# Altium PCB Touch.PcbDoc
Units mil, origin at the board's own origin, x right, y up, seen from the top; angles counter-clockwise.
Board outline 18895 x 844.38 mil, 2 copper layers (Top Layer, Bottom Layer); 105 components, 62 nets, 324 pads, 237 vias.
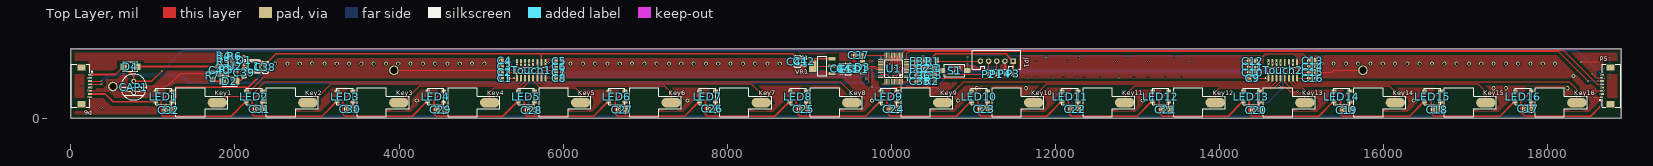
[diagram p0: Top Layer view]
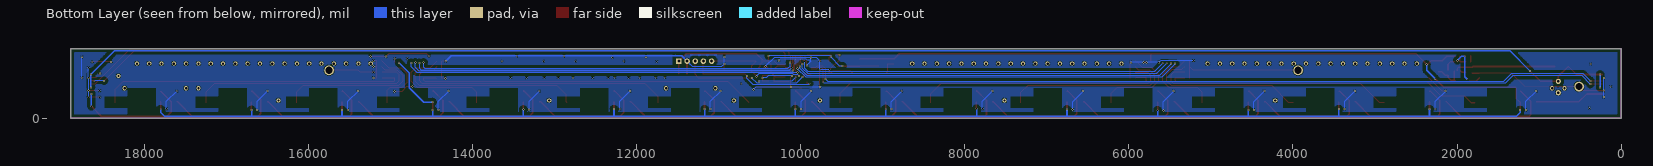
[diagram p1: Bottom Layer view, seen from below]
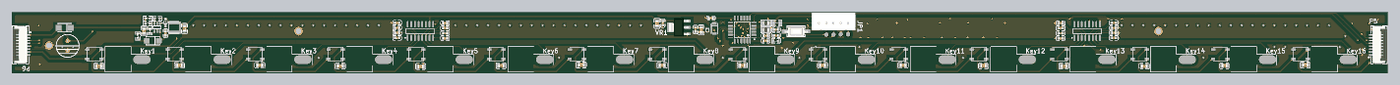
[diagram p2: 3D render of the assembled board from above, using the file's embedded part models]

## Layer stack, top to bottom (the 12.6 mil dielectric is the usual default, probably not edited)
Top Solder: solder mask 0.4, Solder Resist, Dk 3.5
Top Layer: signal copper 1.4
Dielectric 1: dielectric 12.6, FR-4, Dk 4.8
Bottom Layer: signal copper 1.4
Bottom Solder: solder mask 0.4, Solder Resist, Dk 3.5

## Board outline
0,0 18895,0 18895,844.38 0,844.38

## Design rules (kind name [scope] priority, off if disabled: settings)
Clearance CU [InNamedPolygon('POWER_GND_L02_P000')] p1: gap=39.37
Clearance CU2 [InNamedPolygon('POWER_GND_L01_P002')] p2: gap=39.37
Clearance [All] p3: gap=6
PolygonConnect [All] p1: connectstyle=Relief reliefconductorwidth=10 reliefentries=4 polygonreliefangle="90 Angle" airgapwidth=10
RoutingVias [All] p1: holewidth=11.81 width=23.62 viastyle="Through Hole" minholewidth=11.81 minwidth=23.62 maxholewidth=19.68 maxwidth=50
SolderMaskExpansion [All] p1: expansion=4
Width [All] p1: maxlimit=20 minlimit=6 preferedwidth=10
30 further rules are at their usual default settings.

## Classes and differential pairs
component class MCU: C33 C34 C35 C36 C37 FB1 FB2 JP1 P1 P2 P3 P4 R1 R2 S1 U1
component class POWER: C38 C39 C40 C41 C42 C43 C44 CAP1 D1 D2 D3 D4 ESD1 L1 P5 P6 R3 R4 R5 R6 R7 U2 VR1
component class WS2812: C1 C2 C3 C4 C5 C6 C7 C8 C9 C10 C11 C12 C13 C14 C15 C16 C17 C18 C19 C20 C21 C22 C23 C24 C25 C26 C27 C28 C29 C30 C31 C32 Key1 Key2 Key3 Key4 Key5 Key6 Key7 Key8 Key9 Key10 Key11 Key12 Key13 Key14 Key15 Key16 LED1 LED2 LED3 LED4 LED5 LED6 LED7 LED8 LED9 LED10 LED11 LED12 LED13 LED14 LED15 LED16 Touch1 Touch2

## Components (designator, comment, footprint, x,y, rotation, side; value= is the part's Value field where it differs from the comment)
C1 "10pF (100) 5% 50V" 0603_C 5290,489.38 r180 top
C2 "10pF (100) 5% 50V" 0603_C 5290,559.38 r180 top
C3 "10pF (100) 5% 50V" 0603_C 5290,629.38 r180 top
C4 "10pF (100) 5% 50V" 0603_C 5290,699.38 r180 top
C5 "10pF (100) 5% 50V" 0603_C 5950,694.38 r0 top
C6 "10pF (100) 5% 50V" 0603_C 5950,624.38 r0 top
C7 "10pF (100) 5% 50V" 0603_C 5950,554.38 r0 top
C8 "10pF (100) 5% 50V" 0603_C 5950,484.38 r0 top
C9 "10pF (100) 5% 50V" 0603_C 14405,484.38 r180 top
C10 "10pF (100) 5% 50V" 0603_C 14405,554.38 r180 top
C11 "10pF (100) 5% 50V" 0603_C 14405,624.38 r180 top
C12 "10pF (100) 5% 50V" 0603_C 14405,694.38 r180 top
C13 "10pF (100) 5% 50V" 0603_C 15135,699.38 r0 top
C14 "10pF (100) 5% 50V" 0603_C 15135,629.38 r0 top
C15 "10pF (100) 5% 50V" 0603_C 15135,559.38 r0 top
C16 "10pF (100) 5% 50V" 0603_C 15135,489.38 r0 top
C17 "10uF (106) 10% 25V" 0805_C 17765,114.38 r0 top
C18 "10uF (106) 10% 25V" 0805_C 16656.67,104.38 r0 top
C19 "10uF (106) 10% 25V" 0805_C 15553.33,99.38 r0 top
C20 "10uF (106) 10% 25V" 0805_C 14450,99.38 r0 top
C21 "10uF (106) 10% 25V" 0805_C 13345,105 r0 top
C22 "10uF (106) 10% 25V" 0805_C 12240,110 r0 top
C23 "10uF (106) 10% 25V" 0805_C 11135,110 r0 top
C24 "10uF (106) 10% 25V" 0805_C 10030,110 r0 top
C25 "10uF (106) 10% 25V" 0805_C 8930,110 r0 top
C26 "10uF (106) 10% 25V" 0805_C 7820,115 r0 top
C27 "10uF (106) 10% 25V" 0805_C 6720,105 r0 top
C28 "10uF (106) 10% 25V" 0805_C 5615,95 r0 top
C29 "10uF (106) 10% 25V" 0805_C 4510,100 r0 top
C30 "10uF (106) 10% 25V" 0805_C 3405,110 r0 top
C31 "10uF (106) 10% 25V" 0805_C 2300,110 r0 top
C32 "10uF (106) 10% 25V" 0805_C 1195,99.38 r0 top
C33 "100nF (104) 10% 50V" 0603_C 10495,524.38 r0 top
C34 "100nF (104) 10% 50V" 0603_C 10495,604.38 r180 top
C35 "100nF (104) 10% 50V" 0603_C 10355,449.38 r0 top
C36 "100nF (104) 10% 50V" 0603_C 10355,519.38 r0 top
C37 "100nF (104) 10% 50V" 0603_C 9600,764.38 r180 top
C38 "22uF (226) 20% 25V" 0805_C 2370,619.38 r270 top
C39 "22nF (223) 10% 50V" 0603_C 2110,554.38 r270 top
C40 "10uF (106) 10% 25V" 0805_C 1815,584.38 r90 top
C41 "10uF (106) 10% 25V" 0805_C 8860,689.38 r90 top
C42 "100nF (104) 10% 50V" 0603_C 8940,694.38 r90 top
C43 "10uF (106) 10% 25V" 0805_C 9470,599.38 r90 top
C44 "100nF (104) 10% 50V" 0603_C 9390,604.38 r90 top
CAP1 "CAP" 8X12_CAP 765,379.38 r270 top
D1 "1N4148WS T4" SOD-323 2110,704.38 r90 top
D2 "SS210" SMA(DO-214AC)_S1 1935,449.38 r180 top
D3 "ZMM3V3" LL-34 9650,619.38 r270 top
D4 "M7" SMA(DO-214AC)_S1 725,629.38 r180 top
ESD1 "ESD5Z12T" SOD-523 9550,569.38 r90 top
FB1 "100Ω ±25% 100MHz" 0805_L 10355,694.38 r180 top
FB2 "100Ω ±25% 100MHz" 0805_L 10355,599.38 r180 top
JP1 "HDR-1X5" XH2.54-LI-5P 11285,694.38 r180 top
Key1 "TP" SPRING_TOUCH 1785,189.38 r90 top
Key2 "TP" SPRING_TOUCH 2888.33,189.38 r90 top
Key3 "TP" SPRING_TOUCH 3996.67,189.38 r90 top
Key4 "TP" SPRING_TOUCH 5105,189.38 r90 top
Key5 "TP" SPRING_TOUCH 6213.33,189.38 r90 top
Key6 "TP" SPRING_TOUCH 7316.67,189.38 r90 top
Key7 "TP" SPRING_TOUCH 8415,189.38 r90 top
Key8 "TP" SPRING_TOUCH 9518.33,189.38 r90 top
Key9 "TP" SPRING_TOUCH 10626.67,189.38 r90 top
Key10 "TP" SPRING_TOUCH 11735,189.38 r90 top
Key11 "TP" SPRING_TOUCH 12843.33,189.38 r90 top
Key12 "TP" SPRING_TOUCH 13946.67,189.38 r90 top
Key13 "TP" SPRING_TOUCH 15040,189.38 r90 top
Key14 "TP" SPRING_TOUCH 16143.33,189.38 r90 top
Key15 "TP" SPRING_TOUCH 17246.67,189.38 r90 top
Key16 "TP" SPRING_TOUCH 18355,189.38 r90 top
L1 "4.7uH ±10%" L_4030 2308.74,553.71 r90 top
LED1 "WS2812B" WS2812 1230.32,362.41 r180 top
LED2 "WS2812B" WS2812 2334.94,362.41 r180 top
LED3 "WS2812B" WS2812 3439.57,362.41 r180 top
LED4 "WS2812B" WS2812 4544.2,362.41 r180 top
LED5 "WS2812B" WS2812 5648.82,362.41 r180 top
LED6 "WS2812B" WS2812 6753.45,362.41 r180 top
LED7 "WS2812B" WS2812 7858.08,362.41 r180 top
LED8 "WS2812B" WS2812 8962.71,362.41 r180 top
LED9 "WS2812B" WS2812 10067.33,362.41 r180 top
LED10 "WS2812B" WS2812 11171.96,362.41 r180 top
LED11 "WS2812B" WS2812 12276.59,362.41 r180 top
LED12 "WS2812B" WS2812 13381.21,362.41 r180 top
LED13 "WS2812B" WS2812 14485.84,362.41 r180 top
LED14 "WS2812B" WS2812 15590.47,362.41 r180 top
LED15 "WS2812B" WS2812 16695.1,362.41 r180 top
LED16 "WS2812B" WS2812 17799.72,362.41 r180 top
P1 "TP" TP 11285,534.38 r180 top
P2 "TP" TP 11185,534.38 r180 top
P3 "TP" TP 11485,539.38 r180 top
P4 "TP" TP 11385,539.38 r180 top
P5 "Header 8" FPC1.0-2H-WS-8P 18765,393.7 r90 top
P6 "Header 8" FPC1.0-2H-WS-8P 130,393.7 r270 top
R1 "10KΩ (1002) ±1%" 0805_R 10505,694.38 r180 top
R2 "10KΩ (1002) ±1%" 0603_R 10495,449.38 r180 top
R3 "100KΩ (1003) ±1%" 0603_R 1895,589.38 r90 top
R4 "2KΩ (2001) ±1%" 0603_R 1865,759.38 r0 top
R5 "7.5KΩ (7501) ±1%" 0603_R 1865,689.38 r180 top
R6 "49.9KΩ (4992) ±1%" 0603_R 1995,754.38 r0 top
R7 "0Ω (0R0) ±1%" 0603_R 1730,519.38 r270 top
S1 "SW-SPST" "TSW SMD-3*6*2.5" 10772.31,580.16 r0 top
Touch1 "BS818A-2" SO-16_N 5610,584.38 r90 top
Touch2 "BS818A-2" SO-16_N 14770,584.38 r90 top
U1 "STM32F030C8T6" LQFP-48_7x7x05P 10030,604.38 r90 top
U2 "MP2359DJ-LF-Z" SOT-23-6 1995,634.38 r90 top
VR1 "AMS1117-3.3" SOT-223 9160,634.38 r0 top

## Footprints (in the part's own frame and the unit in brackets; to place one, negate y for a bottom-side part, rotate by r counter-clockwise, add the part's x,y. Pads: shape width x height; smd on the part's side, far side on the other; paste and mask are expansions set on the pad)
8X12_CAP [mm]
  round 1.6 hole 0.75: 1(-1.75,0) 2(1.75,0)
  silkscreen extent -4,-4 4,4
0603_C [mm]
  rect 0.93x0.98 smd: 1(-0.77,0) 2(0.77,0)
  silkscreen extent -1.53,-0.79 1.54,0.79, body extent -0.8,-0.4 0.8,0.4, height 0.3
0603_R [mm]
  rect 0.93x0.98 smd: 1(-0.77,0) 2(0.77,0)
  silkscreen extent -1.53,-0.79 1.54,0.79, body extent -0.85,-0.4 0.85,0.4, height 0.56
0805_C [mm]
  rect 1.16x1.47 smd: 1(-0.89,0) 2(0.89,0)
  silkscreen extent -1.77,-1.04 1.77,1.04, body extent -1,-0.62 1,0.63, height 0.77
0805_L [mm]
  rect 1.16x1.47 smd: 1(-0.89,0) 2(0.89,0)
  silkscreen extent -1.77,-1.04 1.77,1.03, body extent -1.02,-0.64 1.03,0.64, height 0.6
0805_R [mm]
  rect 1.16x1.47 smd: 1(-0.89,0) 2(0.89,0)
  silkscreen extent -1.77,-1.04 1.77,1.03, body extent -1,-0.62 1,0.63, height 0.49
FPC1.0-2H-WS-8P [mm] "翻盖FPC，脚距1mm，不含脚（长12.9mm，宽5.2mm，高1.96mm）"
  rect 2x2.5 smd: 0(-5.69,0) 0(5.69,0)
  rect 0.5x1.25 smd: 1(-3.5,2.575) 2(-2.5,2.575) 3(-1.5,2.575) 4(-0.5,2.575) 5(0.5,2.575) 6(1.5,2.575) 7(2.5,2.575) 8(3.5,2.575)
  silkscreen extent -6.64,-3.18 6.64,3.31, body extent -6.45,-3.15 6.45,2.85, height 2
L_4030 [mm]
  rect 1.2x3.5 smd: 1(0.3,2) 2(3.7,2)
  silkscreen extent 0,0 4,4
LL-34 [mm]
  rect 0.9x1.5 smd: 1(1.75,0) 2(-1.75,0)
  silkscreen extent -1.8,-1.08 1.8,1.08
LQFP-48_7x7x05P [mm]
  oval 0.28x1.8 smd mask+0.051: 1(-2.75,-4.05) 2(-2.25,-4.05) 3(-1.75,-4.05) 4(-1.25,-4.05) 5(-0.75,-4.05) 6(-0.25,-4.05) 7(0.25,-4.05) 8(0.75,-4.05) 9(1.25,-4.05) 10(1.75,-4.05) 11(2.25,-4.05) 12(2.75,-4.05) 25(2.75,4.05) 26(2.25,4.05) 27(1.75,4.05) 28(1.25,4.05) 29(0.75,4.05) 30(0.25,4.05) 31(-0.25,4.05) 32(-0.75,4.05) 33(-1.25,4.05) 34(-1.75,4.05) 35(-2.25,4.05) 36(-2.75,4.05)
  oval 1.8x0.28 smd mask+0.051: 13(4.05,-2.75) 14(4.05,-2.25) 15(4.05,-1.75) 16(4.05,-1.25) 17(4.05,-0.75) 18(4.05,-0.25) 19(4.05,0.25) 20(4.05,0.75) 21(4.05,1.25) 22(4.05,1.75) 23(4.05,2.25) 24(4.05,2.75) 37(-4.05,2.75) 38(-4.05,2.25) 39(-4.05,1.75) 40(-4.05,1.25) 41(-4.05,0.75) 42(-4.05,0.25) 43(-4.05,-0.25) 44(-4.05,-0.75) 45(-4.05,-1.25) 46(-4.05,-1.75) 47(-4.05,-2.25) 48(-4.05,-2.75)
  silkscreen extent -3.6,-4.43 2.75,2.75
SMA(DO-214AC)_S1 [mm]
  rect 2x2 smd: 1(2.1,0) 2(-2.1,0)
  silkscreen extent -2.35,-1.5 2.35,1.5
SO-16_N [mm] "SOIC, 16-Leads, Body 9.9x3.9mm, Pitch 1.27mm, IPC Medium Density"
  oval 2.2x0.6 smd: 1(-2.4,4.445) 2(-2.4,3.175) 3(-2.4,1.905) 4(-2.4,0.635) 5(-2.4,-0.635) 6(-2.4,-1.905) 7(-2.4,-3.175) 8(-2.4,-4.445) 9(2.4,-4.445) 10(2.4,-3.175) 11(2.4,-1.905) 12(2.4,-0.635) 13(2.4,0.635) 14(2.4,1.905) 15(2.4,3.175) 16(2.4,4.445)
  silkscreen extent -2.52,-5 0.9,5.42, body extent -2,-5 2,5, height 1.75
SOD-323 [mm]
  rect 1x0.83 smd: 1(1.18,0) 2(-1.18,0)
  silkscreen extent -0.4,-0.6 0.4,0.6, body extent -1.35,-0.62 1.35,0.63, height 1.1
SOD-523 [mm]
  rect 0.5x0.4 smd: 1(0,0) 2(1.4,0)
  silkscreen extent 0,-0.51 1.4,0.51
SOT-23-6 [mm]
  rect 1.1x0.6 smd: 1(1.4,-0.95) 2(1.4,0) 3(1.4,0.95) 4(-1.4,0.95) 5(-1.4,0) 6(-1.4,-0.95)
  silkscreen extent -0.5,-1.87 1.72,1.4
SOT-223 [mm]
  rect 2.2x1 smd: 1(3,-2.3) 2(3,0) 3(3,2.3)
  rect 2.2x3.5 smd: 2(-3,0)
  silkscreen extent -1.4,-3 1.4,3, body extent -3.49,-3.24 3.49,3.24, height 1.64
SPRING_TOUCH [mm]
  oval 3x6 smd: 1(0,0)
  silkscreen extent -4.45,-3.17 4.57,12.83
TP [mil]
  round 60 smd mask+11.81: 1(0,0)
"TSW SMD-3*6*2.5" [mm] "3*6*2.5mm"
  rect 2x1.5 smd: 1(-3.996,-0.02) 2(3.937,0)
  silkscreen extent -3.21,-1.9 3.09,1.9, body extent -4,-1.88 4,1.62, height 2.59
WS2812 [mm]
  rect 1.5x0.9 smd: 1(0,4.15) 2(0,0.85) 3(4.953,0.85) 4(5,4.15)
  silkscreen extent 0,0 5,5
XH2.54-LI-5P [mm] "接插件，5P"
  rect 1.7x1.7 hole 0.9: 1(-5.08,0)
  round 1.7 hole 0.9: 2(-2.54,0) 3(0,0) 4(2.54,0) 5(5.08,0)
  silkscreen extent -7.48,-3.45 7.52,2.49, body extent -7.58,-3.3 7.58,2.4, height 7.03

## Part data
C1 C2 C3 C4 C5 C6 C7 C8 C9 C10 C11 C12 C13 C14 C15 C16: library part "0603 10pF (100) 5% 50V", "贴片电容"
C17 C18 C19 C20 C21 C22 C23 C24 C25 C26 C27 C28 C29 C30 C31 C32 C40 C41 C43: library part "0805 10uF (106) 10% 25V", "贴片电容"
C33 C34 C35 C36 C37 C42 C44: library part "0603 100nF (104) 10% 50V", "贴片电容"
C38: library part "0805 22uF (226) 20% 25V", "贴片电容"
C39: library part "0603 22nF (223) 10% 50V", "贴片电容"
D1: library part "SOD-323 1N4148WS T4", "二极管"
D2: library part "SMA(DO-214AC) SS210", "二极管"
D3: library part "LL-34 ZMM3V3", "稳压二极管"
D4: library part "SMA(DO-214AC) M7", "二极管"
ESD1: library part ESD-D
FB1 FB2: library part "0805 100Ω 25% 100MHz", "贴片磁珠"
JP1: library part "Header 5", "5P接插件"
L1: library part "0603 4.7uH 10%", "贴片电感"
P5 P6: "Header, 8-Pin"
R1: library part "0805 10KΩ (1002) 1%", "贴片电阻"
R2: library part "0603 10KΩ (1002) 1%", "贴片电阻"
R3: library part "0603 100KΩ (1003) 1%", "贴片电阻"
R4: library part "0603 2KΩ (2001) 1%", "贴片电阻"
R5: library part "0603 7.5KΩ (7501) 1%", "贴片电阻"
R6: library part "0603 49.9KΩ (4992) 1%", "贴片电阻"
R7: library part "0603 0Ω (0R0) 1%", "贴片电阻"
S1: "Single-Pole, Single-Throw Switch"
U1: "ARM"
U2: library part MP2359DJ-LF-Z_[C14259], "DC-DCоƬ"
VR1: library part "SOT-223 AMS1117-3.3", "低压差线性稳压(LDO)"

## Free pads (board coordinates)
  round 118.11 hole 86.61: 0(511.81,385) 0(3937.01,583.63) 0(15748.03,583.63)

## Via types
v1: diameter 23.62, hole 11.81, Top Layer to Bottom Layer, 139 vias
v2: diameter 50, hole 28, Top Layer to Bottom Layer, tented both sides, 70 vias
v3: diameter 19.68, hole 11.81, Top Layer to Bottom Layer, 28 vias

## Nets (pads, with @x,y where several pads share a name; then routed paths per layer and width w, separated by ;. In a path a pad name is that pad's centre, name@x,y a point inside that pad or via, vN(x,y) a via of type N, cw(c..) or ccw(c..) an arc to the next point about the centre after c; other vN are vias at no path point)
BIN0: Touch1.13 U1.21 | length 4603.8
  Top Layer w10: v1(5585,669.38) Touch1.13 ; v1(9950,689.38) 9980.79,720.16 U1.21
  Bottom Layer w10: v1(5585,669.38) 5690,564.38 9905,564.38 9950,609.38 v1(9950,689.38)
BIN1: Touch1.14 U1.20 | length 4690.8
  Top Layer w10: v1(9980,659.38) 10000.47,679.85 U1.20
  Bottom Layer w10: v1(5535,669.38) 5665,539.38 9910,539.38 9980,609.38 v1(9980,659.38)
BIN2: Touch1.15 U1.19 | length 4795.5
  Top Layer w10: v1(5485,664.38) Touch1.15 ; v1(10010,629.38) 10020.16,639.53 U1.19
  Bottom Layer w10: v1(5485,664.38) 5630,519.38 9920,519.38 10010,609.38 v1(10010,629.38)
BIN3: Touch1.16 U1.18 | length 4869.9
  Top Layer w10: v1(10040,604.38) U1.18@10040,757.32
  Bottom Layer w10: v1(5435,664.38) 5435.16,664.53 5600.31,499.38 9935,499.38 v1(10040,604.38)
BIN4: Touch2.13 U1.17 | length 5017.3
  Top Layer w10: v1(10040,554.38) 10035,554.38 10070,589.38 10070,644.38 10059.53,654.85 U1.17
  Bottom Layer w10: v1(10040,554.38) 14675,554.38 14745,624.38 v1(14745,674.38)
BIN5: Touch2.14 U1.16 | length 4874.5
  Top Layer w10: U1.16 10079.21,657.79 10086,651 10086,588.38 v1(10095,579.38)
  Bottom Layer w10: v1(10095,579.38) 10104,570.38 14646,570.38 14695,619.38 v1(14695,678.86)
BIN6: Touch2.15 U1.15 | length 4775.2
  Top Layer w10: U1.15 10098.9,675.48 10110,664.38 v1(10110,614.38)
  Bottom Layer w10: v1(10110,614.38) 10138,586.38 14622,586.38 14645,609.38 v1(14645,674.38)
BIN7: Touch2.16 U1.14 | length 4679
  Top Layer w10: U1.14 10118.58,690.79 v1(10130,679.38)
  Bottom Layer w10: v1(10130,679.38) 10130,634.38 10162,602.38 14578,602.38 14595,619.38 v1(14595,678.86)
DATA_IN: LED1.4 P6.7 | length 842
  Top Layer w20: P6.7 419.72,295.28 515.98,199.02 LED1.4
DATA_OUT: LED16.2 P5.2 | length 1501
  Top Layer w20: LED16.2 17670,199.22 17670,78.5 17723.5,25 18525,25 v1(18645,145)
  Bottom Layer w20: v1(18645,145) v1(18645,295)
GNDA: FB2.2 U1.8 | length 144.8
  Top Layer w10: U1.8 10285.43,633.9 FB2.2
NetC1_1: C1.1 Key1.1 Touch1.1 | length 3906.9
  Top Layer w10: Key1.1@1824.38,189.38 1905,270 2190,270 2365,445 5420,445 5435,460 Touch1.1 5434.49,489.38 C1.1
  Top Layer w20: Key1.1 Key1.1@1824.38,189.38
NetC2_1: C2.1 Key2.1 Touch1.2 | length 2961.1
  Top Layer w10: Key2.1 2944.38,189.38 3175,420 5455,420 5485,450 Touch1.2 5485,529.38 5455,559.38 C2.1
NetC3_1: C3.1 Key3.1 Touch1.3 | length 1984.7
  Top Layer w10: Key3.1 4049.38,189.38 4255,395 5480,395 5535,450 Touch1.3 5535,534.38 5480,589.38 5360.31,589.38 C3.1
NetC4_1: C4.1 Key4.1 Touch1.4 | length 1078.8
  Top Layer w10: Key4.1 5105,315 5160,370 5505,370 5585,450 Touch1.4 5585,534.38 5500,619.38 5400,619.38 C4.1@5320.31,699.06
NetC5_1: C5.1 Key5.1 Touch1.5 | length 1181.5
  Top Layer w10: C5.1 5910,694.38 5830,614.38 5720,614.38 5635,529.38 Touch1.5 5635,455 5720,370 6145,370 6213.33,301.67 Key5.1
NetC6_1: C6.1 Key6.1 Touch1.6 | length 2159.8
  Top Layer w10: C6.1 5879.68,584.38 5745,584.38 5685,524.38 Touch1.6 5685,455 5745,395 7235,395 7316.67,313.33 Key6.1
NetC7_1: C7.1 Key7.1 Touch1.7 | length 3118.4
  Top Layer w10: C7.1 5765,554.38 5735,524.38 Touch1.7 5735,455 5770,420 8290,420 8415,295 Key7.1
NetC8_1: C8.1 Key8.1 Touch1.8 | length 4083.9
  Top Layer w10: C8.1 5914.17,489.89 Touch1.8 5785,455 5795,445 9380,445 9518.33,306.67 Key8.1
NetC9_1: C9.1 Key9.1 Touch2.1 | length 4271.2
  Top Layer w10: Key9.1 10882.29,445 14575,445 14595,465 Touch2.1@14595,484.38 ; C9.1@14435.31,474.38 14445.31,484.38 Touch2.1@14595,484.38 ; Touch2.1 Touch2.1@14595,484.38
NetC10_1: C10.1 Key10.1 Touch2.2 | length 3358.7
  Top Layer w10: Key10.1 11735,260 11895,420 14610,420 14645,455 Touch2.2 14645,534.38 14625.18,554.19 C10.1@14435.31,554.19
NetC11_1: C11.1 Key11.1 Touch2.3 | length 2402
  Top Layer w10: Key11.1 12855,201.04 12855,285 12965,395 14640,395 14695,450 Touch2.3 14695,554.38 14669.18,580.19 14479.18,580.19 14435.31,624.06 C11.1
NetC12_1: C12.1 Key12.1 Touch2.4 | length 1455.8
  Top Layer w10: Key12.1 13946.67,316.67 14000,370 14665,370 14745,450 Touch2.4 14745,559.38 14695,609.38 14520.31,609.38 C12.1
NetC13_1: C13.1 Key13.1 Touch2.5 | length 918.2
  Top Layer w10: Key13.1 15040,340 15010,370 14860,370 14795,435 Touch2.5 14795,544.38 14862,611.38 15016.69,611.38 C13.1
NetC14_1: C14.1 Key14.1 Touch2.6 | length 1853.6
  Top Layer w10: C14.1 15060.69,585.38 14914.23,585.38 14845,516.14 Touch2.6 14845,455 14905,395 16070,395 16143.33,321.67 Key14.1
NetC15_1: C15.1 Key15.1 Touch2.7 | length 2836.6
  Top Layer w10: C15.1 14925,559.38 14895,529.38 Touch2.7 14895,455 14930,420 17150,420 17246.67,323.33 Key15.1
NetC16_1: C16.1 Key16.1 Touch2.8 | length 3808.9
  Top Layer w10: C16.1 14945.51,489.38 Touch2.8 14945,460 14960,445 18265,445 18355,355 Key16.1
NetC39_1: C39.1 D1.2 U2.1 | length 163.9
  Top Layer w20: U2.1 2078.43,689.49 D1.2 C39.1
NetC39_2: C39.2 D2.2 L1.1 U2.6 | length 390
  Top Layer w20: D2.2 D2.2@2032.4,464.1 ; U2.6 D2.2@2032.4,464.1 ; L1.1 2186.14,565.52 2144.69,524.06 C39.2 2110,499.38 2074.72,464.1 D2.2@2032.4,464.1
NetLED1_2: LED1.2 LED2.4 | length 1460.1
  Top Layer w20: LED1.2 1223.94,328.94 1100,205 1100,45 1120,25 1955,25 2129.02,199.02 LED2.4
NetLED2_2: LED2.2 LED3.4 | length 1452.3
  Top Layer w20: LED2.2 2323.94,328.94 2210,215 2210,50 2235,25 3060,25 3234.02,199.02 LED3.4
NetLED3_2: LED3.2 LED4.4 | length 1451.5
  Top Layer w20: LED3.2 3428.94,328.94 3315,215 3315,50 3340,25 4160,25 4334.02,199.02 LED4.4
NetLED4_2: LED4.2 LED5.4 | length 1440.8
  Top Layer w20: LED4.2 4533.94,328.94 4425,220 4425,55 4455,25 5265,25 5439.02,199.02 LED5.4
NetLED5_2: LED5.2 LED6.4 | length 1451.2
  Top Layer w20: LED5.2 5643.88,333.88 5525,215 5525,55 5555,25 6370,25 6544.02,199.02 LED6.4
NetLED6_2: LED6.2 LED7.4 | length 1443.3
  Top Layer w20: LED6.2 6748.7,333.7 6635,220 6635,55 6665,25 7480,25 7654.02,199.02 LED7.4
NetLED7_2: LED7.2 LED8.4 | length 1455.3
  Top Layer w20: LED7.2 7853.51,333.51 7735,215 7735,45 7755,25 8580,25 8754.02,199.02 LED8.4
NetLED8_2: LED8.2 LED9.4 | length 1436.1
  Top Layer w20: LED8.2 8948.94,328.94 8840,220 8840,75 8890,25 9685,25 9859.02,199.02 LED9.4
NetLED9_2: LED9.2 LED10.4 | length 1442.4
  Top Layer w20: LED9.2 10062.33,333.94 10058.94,333.94 9945,220 9945,70 9990,25 10790,25 10964.02,199.02 LED10.4
NetLED10_2: LED10.2 LED11.4 | length 1438.8
  Top Layer w20: LED10.2 11165.45,335.45 11055,225 11055,65 11095,25 11895,25 12069.02,199.02 LED11.4
NetLED11_2: LED11.2 LED12.4 | length 1440.9
  Top Layer w20: LED11.2 12271.59,333.94 12268.94,333.94 12155,220 12155,70 12200,25 12995,25 13169.02,199.02 LED12.4
NetLED12_2: LED12.2 LED13.4 | length 1437
  Top Layer w20: LED12.2 13375.08,335.08 13265,225 13265,65 13305,25 14105,25 14279.02,199.02 LED13.4
NetLED13_2: LED13.2 LED14.4 | length 1449.4
  Top Layer w20: LED13.2 14480.84,333.94 14478.94,333.94 14360,215 14360,65 14400,25 15210,25 15384.02,199.02 LED14.4
NetLED14_2: LED14.2 LED15.4 | length 1443.3
  Top Layer w20: LED14.2 15585.47,333.94 15583.94,333.94 15475,225 15475,50 15500,25 16315,25 16489.02,199.02 LED15.4
NetLED15_2: LED15.2 LED16.4 | length 1432.6
  Top Layer w20: LED15.2 16683.94,328.94 16580,225 16580,60 16615,25 17420,25 17594.02,199.02 LED16.4
NetR2_1: R2.1 U1.44 | length 525.4
  Top Layer w10: U1.44 10060,445.4 v1(10060,499.38)
  Bottom Layer w10: v1(10060,499.38) 10110,449.38 v1(10510,449.38)
NetR3_1: R3.1 U2.4 | length 71
  Top Layer w20: R3.1 1937.4,559.06 U2.4
NetR4_1: R4.1 R5.2 | length 70
  Top Layer w20: R5.2 R4.1
NetR5_1: R5.1 R6.1 U2.3 | length 130.1
  Top Layer w20: R5.1 1957.48,689.38 U2.3 1964.69,696.58 R6.1
NRST: C33.2 JP1.5 R1.1 S1.1 U1.7 | length 1583
  Top Layer w10: v1(10020,514.38) 10030,524.38 10065,524.38 10090,549.38 10110,549.38 10130,569.38 10130,589.38 10154.84,614.22 U1.7 ; C33.2 10550,524.38 10585,559.38 10595,559.38 S1.1@10605,569.38 ; S1.1@10590,569.38 S1.1@10605,569.38 ; JP1.5 R1.1 10595,639.41 10595,599.38 S1.1 S1.1@10605,569.38
  Bottom Layer w10: v1(10020,514.38) 10035,529.38 10085,529.38 10094,538.38 10511,538.38 v1(10540,509.38)
POWER_+3.3V: C34.1 C35.1 C36.1 C37.1 C43.2 C44.2 D3.2 ESD1.2 FB1.1 JP1.1 P3.1 R1.2 U1.1 U1.24 U1.48 VR1.2 | length 3965
  Top Layer w10: VR1.2@9041.89,634.38 VR1.2@9278.11,634.38 ; C43.2 C43.2 ; v1(9490,634.38) 9540,634.38 9549.88,624.49 ESD1.2 ; v1(9630.32,751.88) C37.1@9630.32,764.06 ; D3.2 9650,744.37 C37.1@9630.32,764.06 ; U1.24 9921.18,764.38 C37.1 C37.1@9630.32,764.06 ; U1.48 10320.24,444.93 C35.1 C36.1 ; U1.1 10301.42,496.11 C36.1 ; v1(10390,759.38) v1(10390,759.38) FB1.1 FB1.1@10400,694.38 ; R1.2@10469.96,714.34 R1.2 ; C34.1 10495,634.69 10495,659.38 10469.96,684.41 R1.2 ; C36.1 10356.2,550.89 10356.2,650.58 FB1.1@10400,694.38 ; FB1.1@10400,694.38 R1.2
  Top Layer w20: VR1.2@9278.11,634.38 C43.2 ; R1.2@10469.96,714.34 10540,784.38 11395,784.38 JP1.1 P3.1
  Bottom Layer w10: v1(9490,634.38) 9525,634.38 9630.32,739.69 v1(9630.32,751.88) 9640.63,762.19 10387.19,762.19 v1(10390,759.38)
POWER_+12V: CAP1.1 D4.1 P5.4 P5.8 P6.1 P6.5 | length 19148.8
  Top Layer w20: P6.1 v1(255,531.5) 544.44,531.5 D4.1 ; D4.1@650,624.38 765,509.38 CAP1.1 983.27,448.27 v1(1110,575)
  Bottom Layer w20: v1(255,375) v1(255,531.5) ; v1(1110,575) 1355,820 18362.99,820 v1(18651.5,531.5) 18651.5,376.5 v1(18650,375)
POWER_GND: C1.2 C2.2 C3.2 C4.2 C5.2 C6.2 C7.2 C8.2 C9.2 C10.2 C11.2 C12.2 C13.2 C14.2 C15.2 C16.2 C17.1 C18.1 C19.1 C20.1 C21.1 C22.1 C23.1 C24.1 C25.1 C26.1 C27.1 C28.1 C29.1 C30.1 C31.1 C32.1 C33.1 C34.2 C35.2 C36.2 C37.2 C38.2 C40.1 C41.1 C42.1 C43.1 C44.1 CAP1.2 D3.1 ESD1.1 FB2.1 JP1.2 LED1.3 LED2.3 LED3.3 LED4.3 LED5.3 LED6.3 LED7.3 LED8.3 LED9.3 LED10.3 LED11.3 LED12.3 LED13.3 LED14.3 LED15.3 LED16.3 P4.1 P5.1 P5.3 P5.7 P6.2 P6.6 P6.8 pad.0 R2.2 R7.1 S1.2 Touch1.9 Touch1.12 Touch2.9 Touch2.12 U1.23 U1.47 VR1.1 | length 22217.5
  Top Layer w10: v1(210.35,334.65) P6.6 461.46,334.65 pad.0@511.81,385 ; v1(210.91,490.91) P6.2@215,495 ; pad.0@511.81,385.24 689.95,385.65 839.95,386 1177.4,386.78 1340.31,549.69 R7.1 ; v1(2139.94,328.94) 2179.12,328.94 2343.27,493.09 ; pad.0@3937.01,583.63 5213.94,583.63 C3.2 ; v1(5210,700) 5210.62,699.38 C4.2 C3.2 ; C1.2 C2.2 C3.2 ; Touch1.9 5818.86,678.86 v1(5820,680) ; C8.2 C7.2 C6.2 C5.2@5980.32,680 ; C41.1 8930.28,654.34 C42.1 8940,569.38 8965.55,543.82 VR1.1 9359.76,543.82 C44.1 9610.94,574.06 9634.52,550.48 D3.1 v1(9650,590) 9525,715 v1(9525,771.5) C37.2@9565,771.5 ; v1(9765,380) v1(9765,590) ; v1(9925,644.38) 9925,709.38 9941.42,725.79 U1.23 ; 9985,365.3 10010.3,365.3 10023.58,378.58 v1(10118.58,378.58) ; v1(10105,514.38) 10118.58,500.79 U1.47 v1(10118.58,378.58) ; C35.2 R2.2 C33.1 10459.68,519.38 C36.2 ; FB2.1 10420.66,630 v1(10430,630) 10439.06,630 C34.2 ; v1(10575,350) 10546.42,378.58 v1(10118.58,378.58) ; S1.2 10930,582.85 v1(10930,660) ; v1(14325,694.38) C12.2 C11.2 C10.2 C9.2 v1(14330,484.38) ; v1@14525,754.38 v1(14530,754.38) 14560,784.38 15020.62,784.38 v1(15055,750) v1(15245,750) ; v1(14728.75,385) 14805,385 14865,325 v1(14950,325) ; v1(14945,724.21) Touch2.9 14949.4,683.27 14945.79,686.88 v1@14945.79,734.38 ; v1(15205,489.38) C16.2 C15.2 ; v1(15205,629.38) C14.2 ; v1(15205,699.38) C13.2 C14.2 ; pad.0@15748.03,583.63 15393.63,583.63 15369.38,559.38 v1(15205,559.38) C15.2 ; v1(18405,685) v1(18635,685) ; v1(18540,545) 18592.87,492.13 P5.7 v1(18682.13,492.13) ; v1(18545,334.38) 18545.27,334.65 P5.3 ; v1(18546.46,255) 18547.37,255.91 P5.1 ; P5.3@18680,330 v1(18680,335) ; C15.2 C14.2
  Top Layer w20: R7.1 1814.65,549.69 C40.1 ; P4.1 JP1.2
  Bottom Layer w10: v1@210,335 v1(210.35,334.65) ; v1(210.91,255.91) v1@210.91,334.65 ; v1@210.91,335 v1(210.91,490.91) ; v1(1035.32,328.94) 1160,204.26 v1(1160,100) ; v1(2139.94,328.94) 2265,203.88 v1(2265,110) ; v1(3244.57,328.94) 3370,203.51 v1(3370,110) ; v1(4349.2,328.94) 4475,203.14 v1(4475,100) ; v1(5210,700) 5613.86,700 v1(5635,678.86) 5783.86,678.86 v1(5785,680) ; v1(5453.82,328.94) 5580,202.77 v1(5580,95) ; v1(5820,680) v1(5975,680) ; v1(6558.45,328.94) 6685,202.39 v1(6685,105) ; v1(7663.08,328.94) 7785,207.02 v1(7785,115) ; v1(8767.71,328.94) 8895,201.65 v1(8895,110) ; v1(9650,590) v1(9765,590) v3(9765,700) 9804.38,739.38 v1(9875,739.38) ; v1(9765,380) 9766.42,378.58 v1(10118.58,378.58) 10546.42,378.58 v1(10575,350) ; v1(9872.33,328.94) 9995,206.27 v1(9995,110) ; v1(9925,644.38) 9875,694.38 9875,705 ; v1(10105,514.38) 10395.62,514.38 10420,490 v1(10465,490) ; v1(10265,704.38) 10249.38,720 9930,720 9915,705 9875,705 ; v1(10430,630) 10320.62,739.38 v1(9875,739.38) ; v1(10930,744.38) v1(10930,660) 10965,625 11315.62,625 JP1.2 ; v1(10976.96,328.94) 11100,205.9 v1(11100,110) ; 11025.63,765.63 11345,765.63 ; 11525.62,764.38 11530,760 ; v1(12081.59,328.94) 12205,205.53 v1(12205,110) ; v1(13186.21,328.94) 13310,205.16 v1(13310,105) ; v1(14290.84,328.94) 14415,204.78 v1(14415,100) ; 14707.48,384.38 14729.38,384.38 v1(14728.75,385) ; v1(15395.47,328.94) 15520,204.41 v1(15520,100) ; v1(16500.1,328.94) 16625,204.04 v1(16625,100) ; v1(17604.72,328.94) 17730,203.66 v1(17730,115) ; v1(18680,255) v1(18680,335) 18680,490 v1(18682.13,492.13) 18682.13,612.25 v1(18680,614.38) ; v3(18760,495) v3(18760,744.38) ; 9875,705 v1(9875,739.38)
  Bottom Layer w20: JP1.2 11450.62,760 11530,760 14259.38,760 v1(14325,694.38)
  other v1: 14795,725
  other v2: 4215,214.38 7515,214.38 9765,214.38 10815,214.38 13065,214.38 16365,214.38 690,364.38 840,364.38 11040,364.38 11640,364.38 17340,364.38 17490,364.38 18240,364.38 18315,514.38 2490,664.38 2640,664.38 2790,664.38 2940,664.38 3090,664.38 3240,664.38 3390,664.38 3540,664.38 3690,664.38 3840,664.38 3990,664.38 4140,664.38 4290,664.38 4440,664.38 4590,664.38 4740,664.38 4890,664.38 5040,664.38 6090,664.38 6240,664.38 6390,664.38 6540,664.38 6690,664.38 6840,664.38 6990,664.38 7140,664.38 7290,664.38 7440,664.38 7590,664.38 7740,664.38 7890,664.38 8040,664.38 8190,664.38 8340,664.38 8490,664.38 8640,664.38 15240,664.38 15390,664.38 15540,664.38 15690,664.38 15840,664.38 15990,664.38 16140,664.38 16290,664.38 16440,664.38 16590,664.38 16740,664.38 16890,664.38 17040,664.38 17190,664.38 17340,664.38 17490,664.38 17640,664.38 17790,664.38 17940,664.38 18090,664.38
  other v3: 385,120 125,385 10725,420 11655,494.37 11765,494.37 11960,494.37 12095,494.37 12265,494.37 12345,494.37 12535,494.37 12775,494.37 12955,494.37 13125,494.37 13340,494.38 13535,494.37 370,660 11755,690 12155,694.38 12745,694.38 13135,694.38 13640,694.38 12295,740 11885,744.38 13460,754.38 12885,755
SGND: D2.1 R4.2 R7.2 U2.2 | length 556.8
  Top Layer w20: R7.2 1769.68,449.38 D2.1 ; U2.2 v1(1995,704.38)
  Bottom Layer w20: v1(1875,474.38) 1905,504.38 v1(1905,754.38) 1945,754.38 v1(1995,704.38)
SWD_CLK: JP1.4 P2.1 U1.37 | length 1571.8
  Top Layer w10: v1(9895,419.38) 9920,419.38 9921.73,421.11 U1.37 ; v1(10655,514.38) 10675,534.38 P2.1 JP1.4
  Bottom Layer w10: v1(9895,419.38) 9905,409.38 10575,409.38 10655,489.38 v1(10655,514.38)
SWD_DIO: JP1.3 P1.1 U1.34 | length 1664.2
  Top Layer w10: U1.34 9943.9,535.48 v1(9980,499.38) ; v1(10595,489.38) 11240,489.38 P1.1 JP1.3
  Bottom Layer w10: v1(9980,499.38) 10052.81,426.56 10532.19,426.56 v1(10595,489.38)
UART1_RXD: P6.4 U1.31 | length 9895.9
  Top Layer w10: P6.4 232.99,415 v1(375,415) ; v1(9725,440) 9725,595 9744.22,614.22 9790.78,614.22 9810.47,594.53 U1.31
  Bottom Layer w10: v1(375,415) 475,515 1320,515 1410,425 9710,425 v1(9725,440)
UART1_TXD: P6.3 U1.30 | length 9874.3
  Top Layer w10: P6.3 372.76,452.76 v1(375,455) ; v1(9695,475) 9695,600 9728.9,633.9 9801.1,633.9 9820.78,614.22 U1.30
  Bottom Layer w10: v1(375,455) 460,540 1340,540 1435,445 9665,445 v1(9695,475)
UART2_RXD: P5.5 U1.13 | length 8745.5
  Top Layer w10: U1.13 10138.27,798.27 10170,830 18190,830 18606.61,413.39 P5.5
UART2_TXD: P5.6 U1.12 | length 8707.9
  Top Layer w10: U1.12 10189.45,784.45 10219,814 18131,814 v1(18490,455) ; v1(18610,455) 18661.38,455 P5.6
  Bottom Layer w10: v1(18490,455) v1(18610,455)
VBUS: C40.2 D4.2 R3.2 U2.5 | length 1222.8
  Top Layer w20: D4.2 1805.04,629.38 C40.2 1979.96,619.41 1995,604.38 U2.5
VDD_5.0: C17.2 C18.2 C19.2 C20.2 C21.2 C22.2 C23.2 C24.2 C25.2 C26.2 C27.2 C28.2 C29.2 C30.2 C31.2 C32.2 C38.1 C41.2 C42.2 D1.1 L1.2 LED1.1 LED2.1 LED3.1 LED4.1 LED5.1 LED6.1 LED7.1 LED8.1 LED9.1 LED10.1 LED11.1 LED12.1 LED13.1 LED14.1 LED15.1 LED16.1 R6.2 Touch1.10 Touch2.10 VR1.3 | length 28946.7
  Top Layer w20: v1(1230.04,99.38) 1230.32,99.65 LED1.1 1239.02,199.02 1280,240 1280,369.38 1285.62,375 2160,375 v1(2265,480) ; R6.2 2125,754.38 2180,699.38 L1.2 2315,699.38 C38.1@2359.96,654.41 ; v1(2334.94,110.1) LED2.1 ; v1(2370,654.41) 2499.96,784.38 5735,784.38 ; v1(3439.57,110.47) LED3.1 ; v1(4544.2,100.84) LED4.1 ; v1(5648.82,96.22) LED5.1 ; Touch1.10 5735,784.38 ; v1(6753.45,106.59) LED6.1 ; v1(7855.04,115) 7858.08,118.04 LED7.1 ; v1(8962.71,112.33) LED8.1 ; VR1.3 9277.6,724.41 C41.2 8800.04,784.38 5735,784.38 ; v1(10065.04,110) 10067.33,112.29 LED9.1 ; v1(11170.04,110) 11171.96,111.92 LED10.1 ; v1(12275.04,110) 12275.04,197.47 LED11.1 ; v1(13380.04,105) 13381.21,106.17 LED12.1 ; v1(14485.04,99.38) 14485.84,100.18 v1(14485.84,195.84) LED13.1 ; v1(14895,675) Touch2.10 ; v1(15588.37,99.38) 15590.47,101.47 LED14.1 ; v1(16691.71,101.71) C18.2 16695.1,107.77 LED15.1 ; LED16.1 17800.04,198.7 C17.2
  Bottom Layer w20: v1(1230.04,99.38) 1230.04,69.96 1275,25 2335,25 ; v1(2265,480) 2370,585 v1(2370,654.41) ; v1(2334.94,110.1) 2334.94,25.06 2335,25 ; v1(3439.57,110.47) 3439.57,29.57 3435,25 ; v1(4544.2,100.84) 4544.2,29.2 4540,25 ; v1(5648.82,96.22) 5648.82,28.82 5645,25 ; v1(6753.45,106.59) 6753.45,28.45 6750,25 ; v1(7855.04,115) 7855.04,29.96 7860,25 ; v1(8962.71,112.33) 8962.71,25 ; v1(10065.04,110) v1(10065.04,110) 10065,25 ; v1(11170.04,110) v1(11170.04,110) 11170,25 ; v1(12275.04,110) 12275.04,25.04 12275,25 ; v1(13380.04,105) v1(13380.04,105) 13380,25 ; v1(14485.04,99.38) 14485.04,30.04 14480,25 ; v1(14485.84,195.84) 14595.84,195.84 14770,370 14770,550 v1(14895,675) ; v1(15588.37,99.38) 15590,97.75 15590,25 ; v1(16691.71,101.71) 16691.71,26.71 16690,25 ; v1(17800,110) 17800,70 17755,25 16690,25 ; 2335,25 3435,25 ; 3435,25 4540,25 ; 4540,25 5645,25 ; 5645,25 6750,25 ; 6750,25 7860,25 ; 7860,25 8962.71,25 ; 8962.71,25 10065,25 ; 10065,25 11170,25 ; 11170,25 12275,25 ; 12275,25 13380,25 ; 13380,25 14480,25 ; 14480,25 15590,25 ; 15590,25 16690,25
VDDA: FB1.2 U1.9 | length 147.4
  Top Layer w10: U1.9 10279.17,653.59 FB1.2
pads on no net: P5.0 P6.0 Touch1.11 Touch2.11 U1.2 U1.3 U1.4 U1.5 U1.6 U1.10 U1.11 U1.22 U1.25 U1.26 U1.27 U1.28 U1.29 U1.32 U1.33 U1.35 U1.36 U1.38 U1.39 U1.40 U1.41 U1.42 U1.43 U1.45 U1.46

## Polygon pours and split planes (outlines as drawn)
POWER_GND on Bottom Layer "POWER_GND_L02_P000" (hatched 90Degree grid 0 track 10, remove dead copper, pour order 0): 18895,0 18895,844.38 0,844.38 0,0
POWER_GND on Top Layer "POWER_GND_L01_P002" (hatched 90Degree grid 0 track 10, remove dead copper, pour order 2): 0,0 0,844.38 18895,844.38 18895,0

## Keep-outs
Keep-Out Layer:
  the board outline again, w5

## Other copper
Top Layer:
  pour cut-out: 17852.5,370 17852.5,15 18207.5,15 18207.5,115 18487.5,115 18487.5,190 18487.5,265 18207.5,265 18207.5,370
  pour cut-out: 16742.5,370 16742.5,15 17097.5,15 17097.5,115 17377.5,115 17377.5,190 17377.5,265 17097.5,265 17097.5,370
  pour cut-out: 15640,370 15640,15 15995,15 15995,115 16275,115 16275,190 16275,265 15995,265 15995,370
  pour cut-out: 14535,370 14535,15 14890,15 14890,115 15170,115 15170,190 15170,265 14890,265 14890,370
  pour cut-out: 13445,369.38 13445,14.38 13800,14.38 13800,114.38 14080,114.38 14080,189.38 14080,264.38 13800,264.38 13800,369.38
  pour cut-out: 12340,369.38 12340,14.38 12695,14.38 12695,114.38 12975,114.38 12975,189.38 12975,264.38 12695,264.38 12695,369.38
  pour cut-out: 11230,370 11230,15 11585,15 11585,115 11865,115 11865,190 11865,265 11585,265 11585,370
  pour cut-out: 10120,369.38 10120,14.38 10475,14.38 10475,114.38 10755,114.38 10755,189.38 10755,264.38 10475,264.38 10475,369.38
  pour cut-out: 9015,370 9015,15 9370,15 9370,115 9650,115 9650,190 9650,265 9370,265 9370,370
  pour cut-out: 7910,370 7910,15 8265,15 8265,115 8545,115 8545,190 8545,265 8265,265 8265,370
  pour cut-out: 6810,370 6810,15 7165,15 7165,115 7445,115 7445,190 7445,265 7165,265 7165,370
  pour cut-out: 5710,370 5710,15 6065,15 6065,115 6345,115 6345,190 6345,265 6065,265 6065,370
  pour cut-out: 4600,370 4600,15 4955,15 4955,115 5235,115 5235,190 5235,265 4955,265 4955,370
  pour cut-out: 3490,370 3490,15 3845,15 3845,115 4125,115 4125,190 4125,265 3845,265 3845,370
  pour cut-out: 2385,370 2385,15 2740,15 2740,115 3020,115 3020,190 3020,265 2740,265 2740,370
  pour cut-out: 1280,369.38 1280,14.38 1635,14.38 1635,114.38 1915,114.38 1915,189.38 1915,264.38 1635,264.38 1635,369.38
Bottom Layer:
  pour cut-out: 17852.5,370 17852.5,15 18207.5,15 18207.5,115 18487.5,115 18487.5,185 18487.5,265 18207.5,265 18207.5,370
  pour cut-out: 16742.5,370 16742.5,15 17097.5,15 17097.5,115 17377.5,115 17377.5,185 17377.5,265 17097.5,265 17097.5,370
  pour cut-out: 15640,370 15640,15 15995,15 15995,115 16275,115 16275,185 16275,265 15995,265 15995,370
  pour cut-out: 14535,370 14535,15 14890,15 14890,115 15170,115 15170,185 15170,265 14890,265 14890,370
  pour cut-out: 13440,369.38 13440,14.38 13795,14.38 13795,114.38 14075,114.38 14075,184.38 14075,264.38 13795,264.38 13795,369.38
  pour cut-out: 12340,369.38 12340,14.38 12695,14.38 12695,114.38 12975,114.38 12975,184.38 12975,264.38 12695,264.38 12695,369.38
  pour cut-out: 11230,370 11230,15 11585,15 11585,115 11865,115 11865,185 11865,265 11585,265 11585,370
  pour cut-out: 10120,369.38 10120,14.38 10475,14.38 10475,114.38 10755,114.38 10755,184.38 10755,264.38 10475,264.38 10475,369.38
  pour cut-out: 9015,370 9015,15 9370,15 9370,115 9650,115 9650,185 9650,265 9370,265 9370,370
  pour cut-out: 7910,370 7910,15 8265,15 8265,115 8545,115 8545,185 8545,265 8265,265 8265,370
  pour cut-out: 6810,370 6810,15 7165,15 7165,115 7445,115 7445,185 7445,265 7165,265 7165,370
  pour cut-out: 5710,370 5710,15 6065,15 6065,115 6345,115 6345,185 6345,265 6065,265 6065,370
  pour cut-out: 4600,370 4600,15 4955,15 4955,115 5235,115 5235,185 5235,265 4955,265 4955,370
  pour cut-out: 3490,370 3490,15 3845,15 3845,115 4125,115 4125,185 4125,265 3845,265 3845,370
  pour cut-out: 2385,370 2385,15 2740,15 2740,115 3020,115 3020,185 3020,265 2740,265 2740,370
  pour cut-out: 1280,369.38 1280,14.38 1635,14.38 1635,114.38 1915,114.38 1915,184.38 1915,264.38 1635,264.38 1635,369.38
